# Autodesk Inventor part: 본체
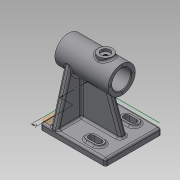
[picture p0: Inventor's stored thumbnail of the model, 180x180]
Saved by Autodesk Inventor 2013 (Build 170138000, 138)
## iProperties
Created: 2019-10
Part Number: 본체
Material: 일반
Document SubType Name: Modeling
Designer: Administrator
Density: 1 g/cm^3
Author: Administrator
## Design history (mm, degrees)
sketch "스케치1"
  geometry: L1 (-50, 43)-(50, 43); L2 (50, 43)-(50, -43); L3 (50, -43)-(-50, -43); L4 (-50, -43)-(-50, 43); L5 (-50, 43)-(50, -43); L6 (50, 43)-(-50, -43); 1 further point
  constraints: 12 end point, 2 midpoint, 2 parallel, 1 horizontal, 1 perpendicular
  dimensions: "d0" = 100 distance of L1.start L1.end; "d2" = 86 distance of L1.end L2.end
extrude "돌출1" new body sketch "스케치1" distance "d3" = 10; taper "d4" = 0 deg
sketch "스케치2"
  geometry: L1 (50, 0)-(-50, 0) reference; L2 (-32, 86)-(-32, 107); L3 (-32, 107)-(50, 107); L4 (50, 107)-(50, 86); L5 (-32, 86)-(50, 86); 2 further points
  constraints: 8 end point, 2 perpendicular, 1 midpoint, 1 parallel, 1 vertical alignment
  dimensions: "d9" = 82 distance of L2.end L3.end; "d10" = 42 diameter of L3 L5; "d11" = 172 diameter of L1 L5
revolve "회전1" sketch "스케치2" stored, may be unused: angle "d12" = 90 deg
sketch "스케치3"
  geometry: L1 (50, 10)-(50, 0) reference; L2 (50, 0)-(-50, 0) reference; L3 (-50, 0)-(-50, 10) reference; L4 (-50, 10)-(50, 10) reference; L5 (50, 65)-(-32, 65) reference; L6 (-32, 65)-(-32, 107) reference; L7 (-32, 107)-(50, 107) reference; L8 (50, 107)-(50, 65) reference; L9 (-32, 86)-(50, 86); L10 (-32, 100.5)-(30, 100.5); L11 (30, 100.5)-(30, 97.5); L12 (30, 97.5)-(50, 97.5); 1 further point
  constraints: 8 end point, 2 midpoint, 2 perpendicular, 2 point on line, 1 parallel
  dimensions: "d13" = 23 diameter of L12 L9; "d15" = 29 diameter of L10 L9; "d16" = 62 distance of L10.start L10.end
revolve "회전2" sketch "스케치3" stored, may be unused: angle "d17" = 90 deg
node "작업 평면1"
sketch "스케치4"
  geometry: L1 (-50, -43)-(-50, 43) reference; L2 (-32, -21)-(-32, 21) reference; C1 r 11 at (-7, 0); 2 further points
  constraints: 1 centre point, 1 horizontal alignment, 1 midpoint
  dimensions: "d20" = 22 diameter of C1; "d21" = 25 distance from line of L2 C1.centre
extrude "돌출2" join sketch "스케치4" stored distance "d22" = 10; taper "d23" = 0 deg
sketch "스케치5"
  geometry: C1 r 11 at (0, 0) reference
hole "구멍1" sketch "스케치5" at (0, 0) diameter "d24" = 4.917; stored, may be unused: countersink angle "d28" = 90 deg, drill point angle "d30" = 118 deg; dims "d25" = 6, "d26" = 14, "d27" = 4, "d29" = 8
sketch "스케치6"
  geometry: C1 r 14.5 at (0, 0) reference; 2 further points
  constraints: 1 horizontal alignment
  dimensions: "d31" = 18 distance of C1.centre point (-18, 0)
hole "구멍2" sketch "스케치6" at (-18, 0) diameter "d32" = 2.459; stored, may be unused: countersink angle "d36" = 90 deg, drill point angle "d38" = 118 deg; dims "d33" = 8, "d34" = 14, "d35" = 4, "d37" = 10
sketch "스케치7"
  geometry: C1 r 11.5 at (0, 0) reference; 2 further points
  constraints: 1 vertical alignment
  dimensions: "d42" = 18 distance of C1.centre point (0, 18)
hole "구멍3" sketch "스케치7" at (0, 18) diameter "d43" = 2.459; stored, may be unused: countersink angle "d47" = 90 deg, drill point angle "d49" = 118 deg; dims "d44" = 8, "d45" = 14, "d46" = 4, "d48" = 10
fillet "모깎기1" dims "d53" = 3
node "작업 평면2"
sketch "스케치9"
  geometry: L1 (10, 83)-(10, 3) reference; L2 (7, 0)-(0, 0) reference; L3 (0, 0)-(0, 86) reference; L4 (0, 86)-(7, 86) reference; L5 (7, 86)-(86, 64); L6 (7, 0)-(86, 22); C1 r 11.5 at (86, 43) reference; A1 r 3 centre (7, 83) between (10, 83) and (7, 86) reference; A2 r 3 centre (7, 3) between (7, 0) and (10, 3) reference; A3 r 21 centre (86, 43) between (86, 64) and (86, 22) reference; 1 further point
  constraints: 4 end point, 2 point on circle, 2 vertical alignment
extrude "돌출3" join sketch "스케치9" distance "d55" = 10; taper "d56" = 0 deg
sketch "스케치10"
  geometry: L1 (-32, 107)-(-18, 107) reference; L2 (-18, 107)-(-18, 110) reference; L3 (-18, 110)-(-14, 110) reference; L4 (-14, 110)-(-14, 106) reference; L5 (-14, 106)-(-9.459, 106) reference; L6 (-9.459, 106)-(-9.459, 100.5) reference; L7 (-9.459, 100.5)-(-32, 100.5) reference; L8 (-32, 100.5)-(-32, 102.77) reference; L9 (-32, 102.77)-(-22, 102.77) reference; L10 (-22, 102.77)-(-21.261, 104) reference; L11 (-21.261, 104)-(-22, 105.229) reference; L12 (-22, 105.229)-(-32, 105.229) reference; L13 (-32, 105.229)-(-32, 107) reference; L14 (50, 97.5)-(30, 97.5) reference; L15 (30, 97.5)-(30, 100.5) reference; L16 (30, 100.5)-(-4.542, 100.5) reference; L17 (-4.542, 100.5)-(-4.542, 106) reference; L18 (-4.542, 106)-(0, 106) reference; L19 (0, 106)-(0, 110) reference; L20 (0, 110)-(4, 110) reference; L21 (4, 110)-(4, 107) reference; L22 (4, 107)-(50, 107) reference; L23 (50, 107)-(50, 105.229) reference; L24 (50, 105.229)-(40, 105.229) reference; L25 (40, 105.229)-(39.261, 104) reference; L26 (39.261, 104)-(40, 102.77) reference; L27 (40, 102.77)-(50, 102.77) reference; L28 (50, 102.77)-(50, 97.5) reference; L29 (-47, 10)-(25, 10) reference; L30 (25, 10)-(25, 65) reference; L31 (25, 65)-(-32, 65) reference; L32 (-32, 65)-(-32, 66.77) reference; L33 (-32, 66.77)-(-22, 66.77) reference; L34 (-22, 66.77)-(-21.261, 68) reference; L35 (-21.261, 68)-(-22, 69.229) reference; L36 (-22, 69.229)-(-32, 69.229) reference; L37 (-32, 69.229)-(-32, 71.5) reference; L38 (-32, 71.5)-(30, 71.5) reference; L39 (30, 71.5)-(30, 74.5) reference; L40 (30, 74.5)-(50, 74.5) reference; L41 (50, 74.5)-(50, 69.229) reference; L42 (50, 69.229)-(40, 69.229) reference; L43 (40, 69.229)-(39.261, 68) reference; L44 (39.261, 68)-(40, 66.77) reference; L45 (40, 66.77)-(50, 66.77) reference; L46 (50, 66.77)-(50, 65) reference; L47 (50, 65)-(35, 65) reference; L48 (35, 65)-(35, 10) reference; L49 (35, 10)-(47, 10) reference; L50 (50, 7)-(50, 0) reference; L51 (50, 0)-(-50, 0) reference; L52 (-50, 0)-(-50, 7) reference; L53 (-35, 10)-(-14.982, 65); A1 r 3 centre (-47, 7) between (-47, 10) and (-50, 7) reference; A2 r 3 centre (47, 7) between (50, 7) and (47, 10) reference; 1 further point
  constraints: 2 end point, 2 point on line
  dimensions: "d57" = 15 distance from line of L52 L53.start; "d58" = 70 deg angle of L29 L53
feature "리브1" sketch "스케치10" dims "d59" = 1, "d60" = 10, "d61" = 0, "d62" = 0, "d63" = 1, "d64" = 1
sketch "스케치11"
  geometry: L1 (35, 5)-(35, -5) reference; L2 (24, -34)-(12, -34); L3 (12, -20)-(24, -20); L4 (50, -43)-(50, 43) reference; A1 r 7 centre (12, -27) between (12, -20) and (12, -34); A2 r 7 centre (24, -27) between (24, -34) and (24, -20); 1 further point
  constraints: 4 end point, 4 point on circle, 4 tangent, 2 centre point, 1 parallel, 1 perpendicular
  dimensions: "d65" = 27 vertical distance of point (0, 0) A2.centre; "d66" = 12 distance of L2.start L2.end; "d67" = 26 distance from line of L4 A2.centre; "d68" = 14 distance between parallel lines of L3 L2
extrude "돌출4" join sketch "스케치11" distance "d69" = 3; taper "d70" = 0 deg
sketch "스케치12"
  geometry: L1 (12, -34)-(24, -34) reference; L2 (24, -20)-(12, -20) reference; L3 (24, -31.5)-(12, -31.5); L4 (12, -22.5)-(24, -22.5); A1 r 7 centre (24, -27) between (24, -34) and (24, -20) reference; A2 r 7 centre (12, -27) between (12, -20) and (12, -34) reference; A3 r 4.5 centre (24, -27) between (24, -31.5) and (24, -22.5); A4 r 4.5 centre (12, -27) between (12, -22.5) and (12, -31.5); 1 further point
  constraints: 4 end point, 4 point on circle, 2 centre point, 3 other
  dimensions: "d71" = 9 distance between parallel lines of L3 L4
extrude "돌출5" cut sketch "스케치12" stored distance "d73" = 3; taper "d74" = 0 deg
fillet "모깎기2" dims "d75" = 3
chamfer "모따기1" distance "d76" = 1; stored, may be unused: second distance "d77" = 2, angle "d78" = 45 deg
chamfer "모따기2" distance "d79" = 1; stored, may be unused: second distance "d80" = 2, angle "d81" = 45 deg
fillet "모깎기3" dims "d82" = 3
fillet "모깎기4" dims "d83" = 3
fillet "모깎기5" dims "d84" = 3
fillet "모깎기6" dims "d85" = 3
fillet "모깎기7" dims "d86" = 3
fillet "모깎기8" dims "d87" = 3
fillet "모깎기9" dims "d88" = 3
node "작업 평면3"
sketch "스케치13"
  geometry: L1 (-50, 40)-(-50, -40) reference; L2 (47, 43)-(-47, 43) reference; 2 further points
  constraints: 1 other
  dimensions: "d90" = 7 distance from line of L1 point (-43, 0); "d91" = 43 distance from line of L2 point (-43, 0)
node "솔리드1"
pattern_circular "원형 패턴1" dims angle "d40" = 360 deg
pattern_circular "원형 패턴2" dims angle "d51" = 360 deg
mirror "대칭1"
node "절단 모서리 투영1"
node "절단 모서리 투영2"
node "절단 모서리 투영3"
other parameters: "d54" = -15, "d89" = 4.5
